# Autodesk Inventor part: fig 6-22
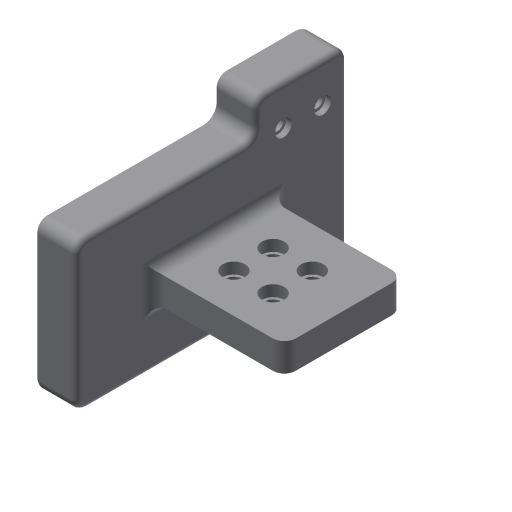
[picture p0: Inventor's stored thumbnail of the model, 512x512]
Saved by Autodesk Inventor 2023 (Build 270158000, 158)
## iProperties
Created: 2004-05
Part Number: fig 6-22
Document SubType Name: Modeling
Designer: CADCIM Technologies
Manufacturer: Standard
Standards Organization: Custom
Density: 1 g/cm^3
Material: Generic
Appearance: Default
Author: CADCIM Technologies
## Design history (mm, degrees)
node "Sketch1"
sketch "Sketch2"
  geometry: L1 (0, 0)-(0, 26.557); L2 (0, 26.557)-(31.986, 26.557); L3 (31.986, 26.557)-(31.986, 32.916); L4 (31.986, 32.916)-(48.42, 32.916); L5 (48.42, 32.916)-(48.42, 0); L6 (48.42, 0)-(0, 0)
  constraints: 12 end point, 4 parallel, 1 perpendicular, 1 vertical
extrude "Extrusion1" new body sketch "Sketch2" distance "d0" = 7.5; taper "d1" = 0 deg
workplane "Work Plane1"
sketch "Sketch3"
  geometry: L1 (7.5, 35.088)-(30.78, 35.088); L2 (30.78, 35.088)-(30.78, 13.871); L3 (30.78, 13.871)-(7.5, 13.871); L4 (7.5, 31.986)-(7.5, 48.42) reference; L5 (7.5, 0)-(7.5, 31.986) reference
  constraints: 6 end point, 2 point on line, 1 horizontal, 1 parallel, 1 perpendicular
extrude "Extrusion2" join sketch "Sketch3" distance "d3" = 5; taper "d4" = 0 deg
fillet "Fillet2" dims "d7" = 2
fillet "Fillet3" dims "d8" = 2
hole "Hole1" diameter "d11" = 3; stored, may be unused: countersink angle "d15" = 90 deg, drill point angle "d17" = 118 deg; dims "d9" = 7, "d10" = 16, "d12" = 6, "d13" = 4, "d14" = 2, "d16" = 8
pattern_linear "Rectangular Pattern1" dims "d20" = 7, "d23" = 7
hole "Hole2" diameter "d26" = 2; stored, may be unused: countersink angle "d30" = 90 deg, drill point angle "d32" = 118 deg; dims "d24" = 5, "d25" = 7, "d27" = 6, "d28" = 3, "d29" = 1, "d31" = 8
pattern_linear "Rectangular Pattern2" dims "d35" = 7
fillet "Fillet4" dims "d36" = 2
fillet "Fillet5" dims "d37" = 1
fillet "Fillet6" dims "d38" = 1
feature "Ɗ耀ƌ耀Ǝ耀Ɛ耀ƒ耀Ɣ耀Ɩ耀Ƙ耀" dims "d0" = 7.5, "d1" = 0, "d2" = -11, "d3" = 5, "d4" = 0, "d7" = 2, "d8" = 2, "d9" = 7, "d10" = 16, "d11" = 3, "d12" = 6, "d13" = 4, "d14" = 2, "d15" = 90 deg, "d16" = 8, "d17" = 118 deg, "d18" = 20, "d20" = 7, "d21" = 20, "d23" = 7, "d24" = 5, "d25" = 7, "d26" = 2, "d27" = 6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
feature "ƶ耀Ƹ耀ƺ耀Ƽ耀ƾ耀ǀ耀ǂ耀Ǆ耀" dims "d0" = 7.5, "d1" = 0, "d2" = -11, "d3" = 5, "d4" = 0, "d7" = 2, "d8" = 2, "d9" = 7, "d10" = 16, "d11" = 3, "d12" = 6, "d13" = 4, "d14" = 2, "d15" = 90 deg, "d16" = 8, "d17" = 118 deg, "d18" = 20, "d20" = 7, "d21" = 20, "d23" = 7, "d24" = 5, "d25" = 7, "d26" = 2, "d27" = 6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
body "Solid1"
